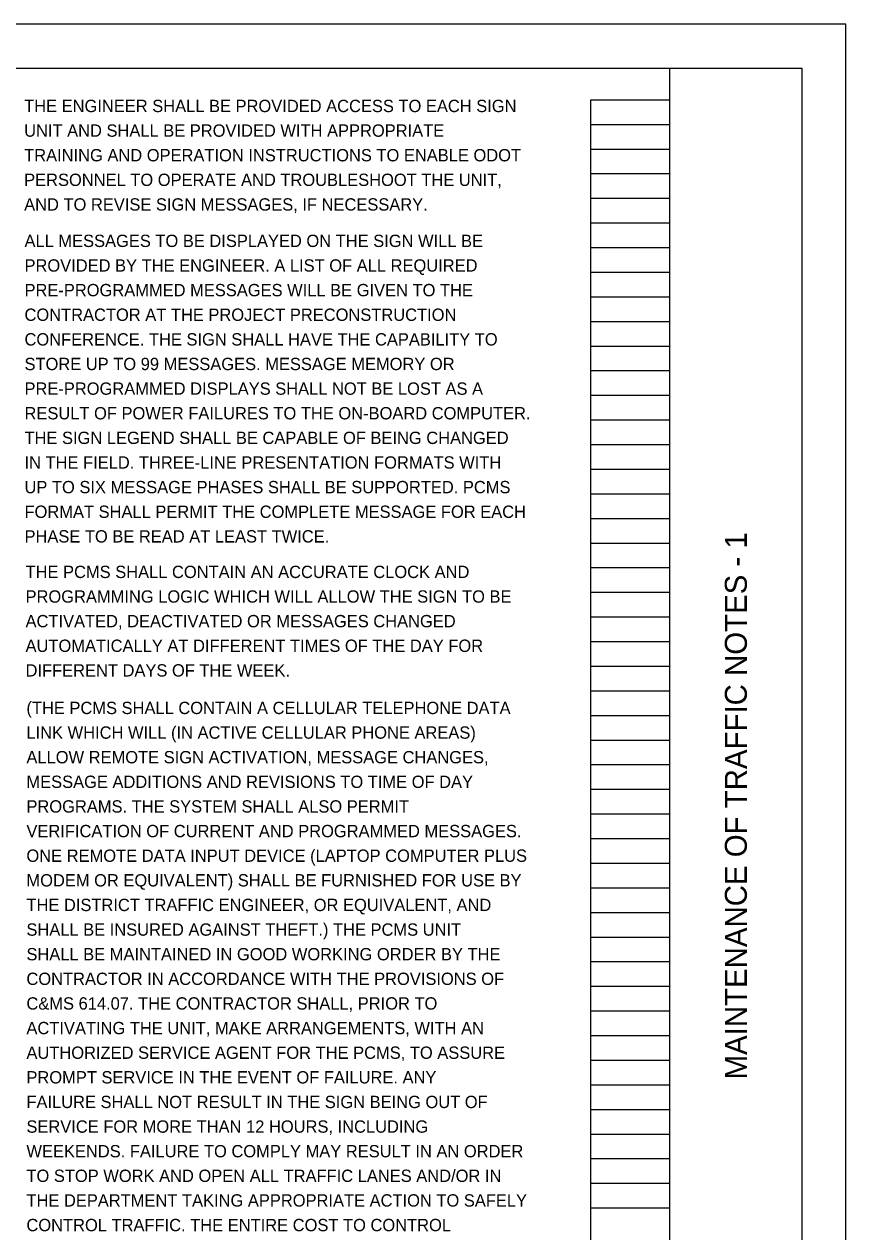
# Model space of a CAD drawing. Extents: x -7 to 34, y -38.9 to 22.
# Drawn here: x 24.66 to 34, y 8.27 to 22 of the extents above; entities that cross this region are included whole.
import ezdxf

# ---------------------------------------------------------------- set-up
doc = ezdxf.new("R2010")
doc.units = 0
for name, color, linetype in [('SH_Border', 7, 'Continuous'), ('SH_Cut_Line', 7, 'Continuous'), ('SH_Data', 7, 'Continuous'), ('SH_Text', 7, 'Continuous')]:
    doc.layers.add(name, color=color, linetype=linetype)

msp = doc.modelspace()

# ---------------------------------------------------------------- linework, layer by layer
at = {"layer": 'SH_Border'}
for p, q in [((31.1, 0.98), (31.1, 21.14)), ((31.1, 21.14), (32, 21.14)), ((32, 0.98), (32, 21.14)), ((31.1, 20.86), (32, 20.86)), ((31.1, 20.58), (32, 20.58)), ((31.1, 20.3), (32, 20.3)), ((31.1, 20.02), (32, 20.02)), ((31.1, 19.74), (32, 19.74)), ((31.1, 19.46), (32, 19.46)), ((31.1, 19.18), (32, 19.18)), ((31.1, 18.9), (32, 18.9)), ((31.1, 18.62), (32, 18.62)), ((31.1, 18.34), (32, 18.34)), ((31.1, 18.06), (32, 18.06)), ((31.1, 17.78), (32, 17.78)), ((31.1, 17.5), (32, 17.5)), ((31.1, 17.22), (32, 17.22)), ((31.1, 16.94), (32, 16.94)), ((31.1, 16.66), (32, 16.66)), ((31.1, 16.38), (32, 16.38)), ((31.1, 16.1), (32, 16.1)), ((31.1, 15.82), (32, 15.82)), ((31.1, 15.54), (32, 15.54)), ((31.1, 15.26), (32, 15.26)), ((31.1, 14.98), (32, 14.98)), ((31.1, 14.7), (32, 14.7)), ((31.1, 14.42), (32, 14.42)), ((31.1, 14.14), (32, 14.14)), ((31.1, 13.86), (32, 13.86)), ((31.1, 13.58), (32, 13.58)), ((31.1, 13.3), (32, 13.3)), ((31.1, 13.02), (32, 13.02)), ((31.1, 12.74), (32, 12.74)), ((31.1, 12.46), (32, 12.46)), ((31.1, 12.18), (32, 12.18)), ((31.1, 11.9), (32, 11.9)), ((31.1, 11.62), (32, 11.62)), ((31.1, 11.34), (32, 11.34)), ((31.1, 11.06), (32, 11.06)), ((31.1, 10.78), (32, 10.78)), ((31.1, 10.5), (32, 10.5)), ((31.1, 10.22), (32, 10.22)), ((31.1, 9.94), (32, 9.94)), ((31.1, 9.66), (32, 9.66)), ((31.1, 9.38), (32, 9.38)), ((31.1, 9.1), (32, 9.1)), ((31.1, 8.82), (32, 8.82)), ((31.1, 8.54), (32, 8.54))]:
    msp.add_line(p, q, dxfattribs=at)
at = {"layer": 'SH_Cut_Line'}
msp.add_line((32, 0.5), (32, 21.5), dxfattribs=at)
msp.add_lwpolyline([(1.5, 21.5), (33.5, 21.5), (33.5, 0.5), (1.5, 0.5)], close=True, dxfattribs=at)
at = {"layer": 'SH_Text'}
msp.add_lwpolyline([(0, 0), (34, 0), (34, 22), (0, 22)], close=True, dxfattribs=at)

# ---------------------------------------------------------------- texts
at = {"layer": 'SH_Border'}
msp.add_text('MAINTENANCE OF TRAFFIC NOTES - 1', height=0.25, rotation=90, dxfattribs=at).set_placement((32.875, 10.001))
at = {"layer": 'SH_Data'}
for s, p in [('THE ENGINEER SHALL BE PROVIDED ACCESS TO EACH SIGN', (24.66, 21)), ('UNIT AND SHALL BE PROVIDED WITH APPROPRIATE', (24.66, 20.72)), ('TRAINING AND OPERATION INSTRUCTIONS TO ENABLE ODOT', (24.66, 20.44)), ('PERSONNEL TO OPERATE AND TROUBLESHOOT THE UNIT,', (24.66, 20.16)), ('AND TO REVISE SIGN MESSAGES, IF NECESSARY.', (24.66, 19.88)), ('ALL MESSAGES TO BE DISPLAYED ON THE SIGN WILL BE', (24.664, 19.466)), ('PROVIDED BY THE ENGINEER. A LIST OF ALL REQUIRED', (24.664, 19.186)), ('PRE-PROGRAMMED MESSAGES WILL BE GIVEN TO THE', (24.664, 18.906)), ('CONTRACTOR AT THE PROJECT PRECONSTRUCTION', (24.664, 18.626)), ('CONFERENCE. THE SIGN SHALL HAVE THE CAPABILITY TO', (24.664, 18.346)), ('STORE UP TO 99 MESSAGES. MESSAGE MEMORY OR', (24.664, 18.066)), ('PRE-PROGRAMMED DISPLAYS SHALL NOT BE LOST AS A', (24.664, 17.786)), ('RESULT OF POWER FAILURES TO THE ON-BOARD COMPUTER.', (24.664, 17.506)), ('THE SIGN LEGEND SHALL BE CAPABLE OF BEING CHANGED', (24.664, 17.226)), ('IN THE FIELD. THREE-LINE PRESENTATION FORMATS WITH', (24.664, 16.946)), ('UP TO SIX MESSAGE PHASES SHALL BE SUPPORTED. PCMS', (24.664, 16.666)), ('FORMAT SHALL PERMIT THE COMPLETE MESSAGE FOR EACH', (24.664, 16.386)), ('PHASE TO BE READ AT LEAST TWICE.', (24.664, 16.106)), ('THE PCMS SHALL CONTAIN AN ACCURATE CLOCK AND', (24.676, 15.702)), ('PROGRAMMING LOGIC WHICH WILL ALLOW THE SIGN TO BE', (24.676, 15.422)), ('ACTIVATED, DEACTIVATED OR MESSAGES CHANGED', (24.676, 15.142)), ('AUTOMATICALLY AT DIFFERENT TIMES OF THE DAY FOR', (24.676, 14.862)), ('DIFFERENT DAYS OF THE WEEK.', (24.676, 14.582)), ('(THE PCMS SHALL CONTAIN A CELLULAR TELEPHONE DATA', (24.686, 14.155)), ('LINK WHICH WILL (IN ACTIVE CELLULAR PHONE AREAS)', (24.686, 13.875)), ('ALLOW REMOTE SIGN ACTIVATION, MESSAGE CHANGES,', (24.686, 13.595)), ('MESSAGE ADDITIONS AND REVISIONS TO TIME OF DAY', (24.686, 13.315)), ('PROGRAMS. THE SYSTEM SHALL ALSO PERMIT', (24.686, 13.035)), ('VERIFICATION OF CURRENT AND PROGRAMMED MESSAGES.', (24.686, 12.755)), ('ONE REMOTE DATA INPUT DEVICE (LAPTOP COMPUTER PLUS', (24.686, 12.475)), ('MODEM OR EQUIVALENT) SHALL BE FURNISHED FOR USE BY', (24.686, 12.195)), ('THE DISTRICT TRAFFIC ENGINEER, OR EQUIVALENT, AND', (24.686, 11.915)), ('SHALL BE INSURED AGAINST THEFT.) THE PCMS UNIT', (24.686, 11.635)), ('SHALL BE MAINTAINED IN GOOD WORKING ORDER BY THE', (24.686, 11.355)), ('CONTRACTOR IN ACCORDANCE WITH THE PROVISIONS OF', (24.686, 11.075)), ('C&MS 614.07. THE CONTRACTOR SHALL, PRIOR TO', (24.686, 10.795)), ('ACTIVATING THE UNIT, MAKE ARRANGEMENTS, WITH AN', (24.686, 10.515)), ('AUTHORIZED SERVICE AGENT FOR THE PCMS, TO ASSURE', (24.686, 10.235)), ('PROMPT SERVICE IN THE EVENT OF FAILURE. ANY', (24.686, 9.955)), ('FAILURE SHALL NOT RESULT IN THE SIGN BEING OUT OF', (24.686, 9.675)), ('SERVICE FOR MORE THAN 12 HOURS, INCLUDING', (24.686, 9.395)), ('WEEKENDS. FAILURE TO COMPLY MAY RESULT IN AN ORDER', (24.686, 9.115)), ('TO STOP WORK AND OPEN ALL TRAFFIC LANES AND/OR IN', (24.686, 8.835)), ('THE DEPARTMENT TAKING APPROPRIATE ACTION TO SAFELY', (24.686, 8.555)), ('CONTROL TRAFFIC. THE ENTIRE COST TO CONTROL', (24.686, 8.275))]:
    msp.add_text(s, height=0.14, dxfattribs=at).set_placement(p)

doc.saveas('drawing.dxf')
